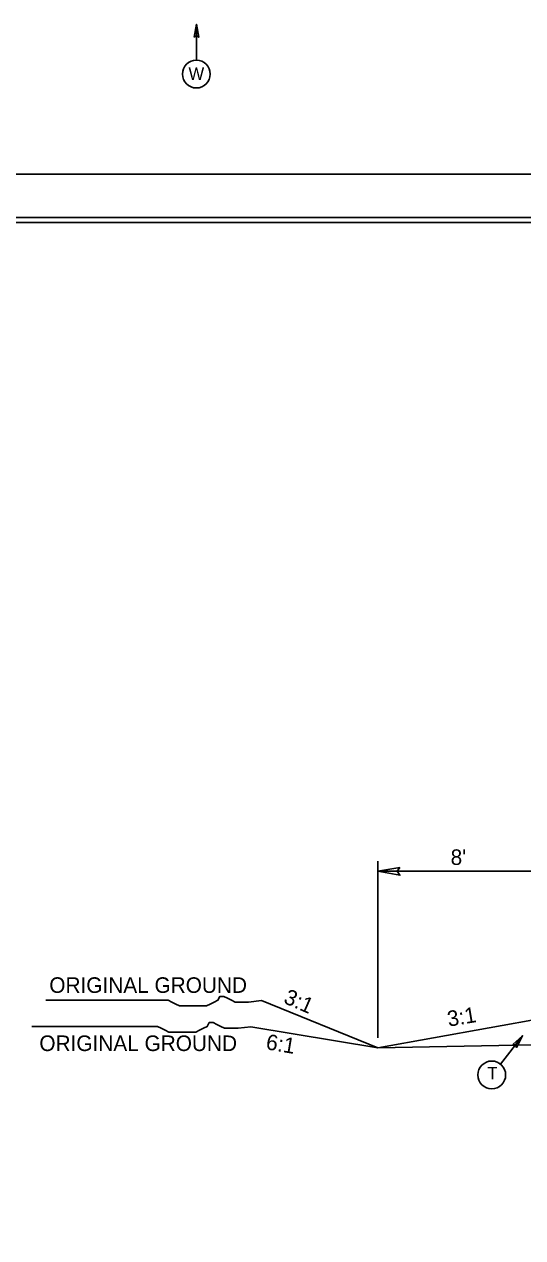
# Model space of a CAD drawing. Extents: x 2111095 to 2115970, y 670428 to 672393.
# Drawn here: x 2112193 to 2112453, y 671663 to 672294 of the extents above; entities that cross this region are included whole.
import ezdxf

# ---------------------------------------------------------------- set-up
doc = ezdxf.new("R2010")
doc.units = 0
for name, color, linetype in [('Old_Level_11', 7, 'Continuous'), ('Old_Level_20', 7, 'Continuous'), ('Prop Leader Line Medium', 7, 'Continuous'), ('Sheet Cutting Line CELL', 7, 'Continuous'), ('Sheet Plot Border Inside CELL', 7, 'Continuous'), ('Sheet Plot Border Outside CELL', 7, 'Continuous'), ('Sheet Typical CELL', 7, 'Continuous'), ('Typical Hinge Slope Arterial CELL', 7, 'Continuous'), ('Typical Pavement Slope CELL', 7, 'Continuous'), ('Typical Terminator CELL', 7, 'Continuous')]:
    doc.layers.add(name, color=color, linetype=linetype)

msp = doc.modelspace()

# ---------------------------------------------------------------- linework, layer by layer
at = {"layer": 'Old_Level_11'}
for p, q in [((2112283.12, 672275.37), (2112283.12, 672294.06)), ((2112441.46, 671753.15), (2112452.94, 671767.91))]:
    msp.add_line(p, q, dxfattribs=at)
for points in [[(2112281.96, 672287.38), (2112283.12, 672294.06), (2112284.3, 672287.34), (2112283.12, 672288.19)], [(2112447.92, 671763.34), (2112452.94, 671767.91), (2112449.75, 671761.87), (2112449.34, 671763.27)]]:
    msp.add_lwpolyline(points, close=True, dxfattribs=at)
for centre in [(2112283.12, 672268.15), (2112436.9, 671747.55)]:
    msp.add_circle(centre, 7.22, dxfattribs=at)
at = {"layer": 'Prop Leader Line Medium'}
for p, q in [((2112377.61, 671766.85), (2112377.61, 671858.67)), ((2112377.61, 671853.48), (2112464.58, 671853.48))]:
    msp.add_line(p, q, dxfattribs=at)
at = {"layer": 'Sheet Cutting Line CELL'}
msp.add_line((2113267.52, 672216.03), (2111583.52, 672216.03), dxfattribs=at)
at = {"layer": 'Sheet Plot Border Inside CELL'}
msp.add_lwpolyline([(2113263.02, 672193.58), (2111596.52, 672193.58), (2111596.52, 671138.48), (2113263.02, 671138.48)], close=True, dxfattribs=at)
at = {"layer": 'Sheet Plot Border Outside CELL'}
msp.add_lwpolyline([(2113267.52, 672216.03), (2111583.52, 672216.03), (2111583.52, 671116.03), (2113267.52, 671116.03)], close=True, dxfattribs=at)
at = {"layer": 'Sheet Typical CELL'}
msp.add_lwpolyline([(2113250.52, 672191.03), (2111750.52, 672191.03), (2111750.52, 671141.03), (2113250.52, 671141.03)], close=True, dxfattribs=at)
at = {"layer": 'Typical Hinge Slope Arterial CELL'}
for p, q in [((2112316.96, 671786.25), (2112377.61, 671761.61)), ((2112377.61, 671761.61), (2112464.58, 671777.25)), ((2112377.61, 671761.61), (2112311.43, 671772.64))]:
    msp.add_line(p, q, dxfattribs=at)
for points in [[(2112316.96, 671786.25), (2112310.31, 671785.42), (2112308.31, 671785.42), (2112305.31, 671785.42), (2112303.32, 671785.42), (2112301.32, 671786.42), (2112299.33, 671787.42), (2112297.33, 671788.42), (2112295.34, 671788.42), (2112294.34, 671786.42), (2112292.34, 671785.42), (2112290.34, 671784.42), (2112288.35, 671783.43), (2112286.35, 671783.43), (2112284.36, 671783.43), (2112282.36, 671783.43), (2112280.37, 671783.43), (2112278.37, 671783.43), (2112276.38, 671783.43), (2112274.38, 671783.43), (2112272.38, 671784.42), (2112270.39, 671785.42), (2112268.39, 671786.42), (2112265.4, 671786.42), (2112263.4, 671786.42), (2112204.73, 671786.42)], [(2112311.43, 671772.64), (2112304.78, 671771.82), (2112302.79, 671771.82), (2112299.79, 671771.82), (2112297.79, 671771.82), (2112295.8, 671772.81), (2112293.8, 671773.81), (2112291.81, 671774.81), (2112289.81, 671774.81), (2112288.81, 671772.81), (2112286.81, 671771.82), (2112284.82, 671770.81), (2112282.82, 671769.82), (2112280.83, 671769.82), (2112278.83, 671769.82), (2112276.83, 671769.82), (2112274.84, 671769.82), (2112272.84, 671769.82), (2112270.85, 671769.82), (2112268.85, 671769.82), (2112266.86, 671770.81), (2112264.86, 671771.82), (2112262.87, 671772.81), (2112259.87, 671772.81), (2112257.87, 671772.81), (2112197.46, 671772.81)]]:
    msp.add_lwpolyline(points, dxfattribs=at)
at = {"layer": 'Typical Pavement Slope CELL'}
msp.add_line((2112377.61, 671761.61), (2112499.18, 671764.04), dxfattribs=at)
at = {"layer": 'Typical Terminator CELL'}
msp.add_lwpolyline([(2112389, 671855.44), (2112377.61, 671853.48), (2112389.07, 671851.45), (2112387.61, 671853.48)], close=True, dxfattribs=at)

# ---------------------------------------------------------------- texts
at = {"layer": 'Old_Level_20'}
for s, p in [('W', (2112279.02, 672265.15)), ('T', (2112434.63, 671745.24))]:
    msp.add_text(s, height=6.46, dxfattribs=at).set_placement(p)
at = {"layer": 'Prop Leader Line Medium'}
msp.add_text("8'", height=8.1, rotation=360, dxfattribs=at).set_placement((2112415.48, 671856.77))
at = {"layer": 'Typical Hinge Slope Arterial CELL'}
for s, rotation, p in [('ORIGINAL GROUND', 360, (2112206.54, 671790.23)), ('3:1', 336.4435, (2112328.01, 671785.18)), ('3:1', 9.46232, (2112414.45, 671772.61)), ('ORIGINAL GROUND', 360, (2112201.36, 671759.97)), ('6:1', 350.53768, (2112318.96, 671760.93))]:
    msp.add_text(s, height=8.1, rotation=rotation, dxfattribs=at).set_placement(p)

doc.saveas('drawing.dxf')
